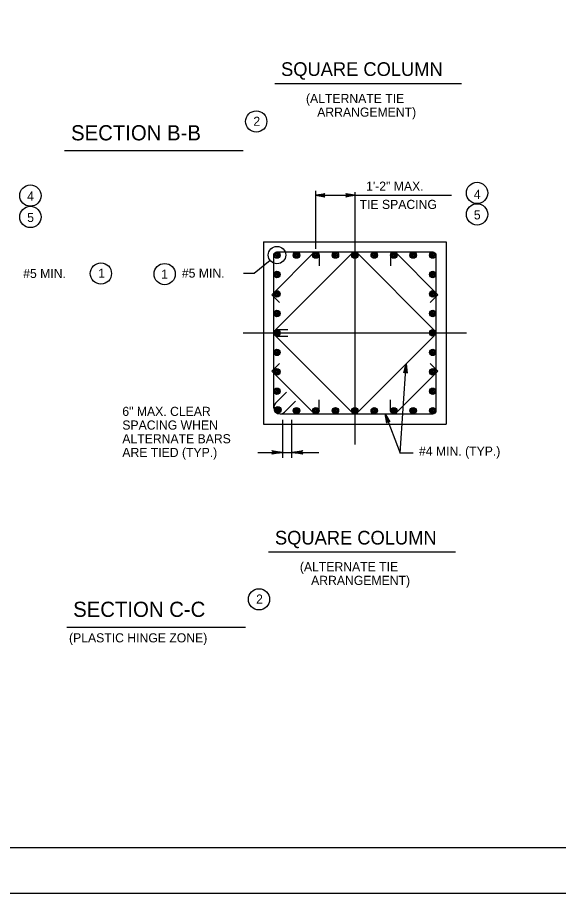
# Model space of a CAD drawing. Extents: x 646165 to 651486, y 296916 to 299292.
# Drawn here: x 648407.1 to 648585, y 296916.2 to 297204.4 of the extents above; entities that cross this region are included whole.
import ezdxf

# ---------------------------------------------------------------- set-up
doc = ezdxf.new("R2010")
doc.units = 0
for name, color, linetype in [('2', 7, 'Continuous'), ('50', 7, 'Continuous'), ('51', 7, 'Continuous'), ('52', 7, 'Continuous'), ('53', 7, 'Continuous'), ('54', 7, 'Continuous'), ('PLT-BNDY', 7, 'Continuous')]:
    doc.layers.add(name, color=color, linetype=linetype)

msp = doc.modelspace()

# ---------------------------------------------------------------- linework, layer by layer
at = {"layer": '2'}
msp.add_line((648933.59, 296931.25), (648147.59, 296931.25), dxfattribs=at)
at = {"layer": '50'}
for p, q in [((648518.06, 297147.01), (648518.06, 297064)), ((648481.39, 297100.67), (648554.73, 297100.67))]:
    msp.add_line(p, q, dxfattribs=at)
at = {"layer": '51'}
for p, q in [((648488.06, 297130.67), (648488.06, 297070.67)), ((648488.06, 297130.67), (648548.06, 297130.67)), ((648548.06, 297130.67), (648548.06, 297070.67)), ((648488.06, 297070.67), (648548.06, 297070.67))]:
    msp.add_line(p, q, dxfattribs=at)
at = {"layer": '52'}
for p, q in [((648505.26, 297128.33), (648505.26, 297147.42)), ((648505.26, 297145.93), (648549.84, 297145.93)), ((648490.23, 297124.47), (648484.91, 297120.16)), ((648484.91, 297120.16), (648481.41, 297120.16)), ((648532.95, 297061.15), (648534.91, 297090.47)), ((648528.03, 297074), (648532.95, 297061.15)), ((648494.37, 297059.52), (648494.37, 297072.12)), ((648497.33, 297059.52), (648497.33, 297072.12)), ((648486.21, 297061.37), (648494.37, 297061.37)), ((648494.37, 297061.37), (648497.33, 297061.37)), ((648497.33, 297061.37), (648506.23, 297061.37)), ((648537.19, 297061.15), (648532.95, 297061.15))]:
    msp.add_line(p, q, dxfattribs=at)
for points in [[(648505.26, 297145.93), (648508.24, 297146.49), (648508.13, 297146.41), (648508.01, 297146.33), (648507.95, 297146.23), (648507.89, 297146.13), (648507.88, 297146.03), (648507.86, 297145.93), (648507.88, 297145.83), (648507.89, 297145.73), (648507.95, 297145.63), (648508.01, 297145.53), (648508.13, 297145.45), (648508.24, 297145.37), (648505.26, 297145.93), (648508.13, 297145.45), (648508.01, 297145.53), (648505.26, 297145.93), (648507.95, 297145.63), (648507.89, 297145.73), (648505.26, 297145.93), (648507.88, 297145.83), (648507.86, 297145.93), (648505.26, 297145.93), (648507.88, 297146.03), (648507.89, 297146.13), (648505.26, 297145.93), (648507.95, 297146.23), (648508.01, 297146.33), (648505.26, 297145.93), (648508.13, 297146.41)], [(648518.06, 297145.93), (648515.08, 297145.37), (648515.19, 297145.45), (648515.31, 297145.53), (648515.37, 297145.63), (648515.42, 297145.73), (648515.44, 297145.83), (648515.46, 297145.93), (648515.44, 297146.03), (648515.42, 297146.13), (648515.37, 297146.23), (648515.31, 297146.33), (648515.19, 297146.41), (648515.08, 297146.49), (648518.06, 297145.93), (648515.19, 297146.41), (648515.31, 297146.33), (648518.06, 297145.93), (648515.37, 297146.23), (648515.42, 297146.13), (648518.06, 297145.93), (648515.44, 297146.03), (648515.46, 297145.93), (648518.06, 297145.93), (648515.44, 297145.83), (648515.42, 297145.73), (648518.06, 297145.93), (648515.37, 297145.63), (648515.31, 297145.53), (648518.06, 297145.93), (648515.19, 297145.45)], [(648534.91, 297090.47), (648535.27, 297087.46), (648535.2, 297087.58), (648535.13, 297087.69), (648535.03, 297087.76), (648534.94, 297087.83), (648534.84, 297087.85), (648534.74, 297087.87), (648534.64, 297087.86), (648534.54, 297087.85), (648534.43, 297087.8), (648534.33, 297087.75), (648534.24, 297087.64), (648534.16, 297087.53), (648534.91, 297090.47), (648534.24, 297087.64), (648534.33, 297087.75), (648534.91, 297090.47), (648534.43, 297087.8), (648534.54, 297087.85), (648534.91, 297090.47), (648534.64, 297087.86), (648534.74, 297087.87), (648534.91, 297090.47), (648534.84, 297087.85), (648534.94, 297087.83), (648534.91, 297090.47), (648535.03, 297087.76), (648535.13, 297087.69), (648534.91, 297090.47), (648535.2, 297087.58)], [(648528.03, 297074), (648529.62, 297071.42), (648529.51, 297071.5), (648529.39, 297071.57), (648529.28, 297071.59), (648529.16, 297071.61), (648529.06, 297071.59), (648528.96, 297071.57), (648528.87, 297071.52), (648528.79, 297071.47), (648528.72, 297071.38), (648528.64, 297071.29), (648528.61, 297071.15), (648528.58, 297071.02), (648528.03, 297074), (648528.61, 297071.15), (648528.64, 297071.29), (648528.03, 297074), (648528.72, 297071.38), (648528.79, 297071.47), (648528.03, 297074), (648528.87, 297071.52), (648528.96, 297071.57), (648528.03, 297074), (648529.06, 297071.59), (648529.16, 297071.61), (648528.03, 297074), (648529.28, 297071.59), (648529.39, 297071.57), (648528.03, 297074), (648529.51, 297071.5)]]:
    msp.add_lwpolyline(points, dxfattribs=at)
for centre, radius in [((648485.63, 297170.22), 3.5), ((648411.37, 297145.85), 3.5), ((648558.25, 297146.71), 3.5), ((648411.37, 297138.81), 3.5), ((648558.25, 297139.66), 3.5), ((648492.46, 297126.27), 2.87), ((648434.55, 297120.21), 3.5), ((648455.52, 297120.01), 3.5), ((648486.55, 297013.02), 3.5)]:
    msp.add_circle(centre, radius, dxfattribs=at)
at = {"layer": '53'}
for p, q in [((648491.71, 297182.7), (648553.12, 297182.7)), ((648422.61, 297160.67), (648481.36, 297160.67)), ((648489.71, 297028.65), (648551.12, 297028.65)), ((648423.31, 297003.91), (648482.06, 297003.91))]:
    msp.add_line(p, q, dxfattribs=at)
at = {"layer": '54'}
for p, q in [((648490.74, 297113.21), (648504.5, 297127.02)), ((648491.39, 297076.07), (648491.4, 297126.27)), ((648492, 297101.63), (648517.3, 297127.02)), ((648492.46, 297127.34), (648543.66, 297127.34)), ((648506.33, 297126.27), (648506.33, 297122.74)), ((648544.34, 297101.4), (648518.81, 297127.02)), ((648529.79, 297126.27), (648529.79, 297122.74)), ((648545.38, 297113.21), (648531.61, 297127.02)), ((648544.73, 297126.27), (648544.73, 297075.07)), ((648493.24, 297110.71), (648490.74, 297113.21)), ((648542.88, 297110.71), (648545.38, 297113.21)), ((648491.75, 297099.96), (648517.3, 297074.32)), ((648492.46, 297101.74), (648495.99, 297101.74)), ((648492.46, 297099.6), (648495.99, 297099.6)), ((648544.12, 297099.71), (648518.81, 297074.32)), ((648493.24, 297090.62), (648490.74, 297088.13)), ((648542.88, 297090.62), (648545.38, 297088.13)), ((648490.74, 297088.13), (648504.5, 297074.32)), ((648545.38, 297088.13), (648531.61, 297074.32)), ((648492, 297077.53), (648495.61, 297081.15)), ((648494.92, 297074.61), (648498.54, 297078.22)), ((648506.33, 297075.07), (648506.33, 297078.6)), ((648529.79, 297075.07), (648529.79, 297078.6)), ((648493.46, 297074), (648543.66, 297074))]:
    msp.add_line(p, q, dxfattribs=at)
for points in [[(648490.96, 297061.8), (648491.09, 297061.55), (648494.37, 297061.37), (648490.96, 297061.8), (648490.79, 297061.95), (648494.37, 297061.37), (648491.09, 297061.21), (648490.97, 297060.97), (648494.37, 297061.37), (648490.79, 297060.8), (648490.97, 297060.97)], [(648500.74, 297060.94), (648500.61, 297061.19), (648497.33, 297061.37), (648500.74, 297060.94), (648500.91, 297060.79), (648497.33, 297061.37), (648500.61, 297061.53), (648500.73, 297061.78), (648497.33, 297061.37), (648500.91, 297061.94), (648500.73, 297061.78)]]:
    msp.add_lwpolyline(points, dxfattribs=at)
for centre, radius in [((648492.46, 297126.27), 1.07), ((648492.46, 297126.27), 0.8), ((648492.46, 297126.27), 0.533), ((648492.46, 297126.27), 0.267), ((648498.86, 297126.27), 1.07), ((648498.86, 297126.27), 0.8), ((648498.86, 297126.27), 0.533), ((648498.86, 297126.27), 0.267), ((648505.26, 297126.27), 1.07), ((648505.26, 297126.27), 0.8), ((648505.26, 297126.27), 0.533), ((648505.26, 297126.27), 0.267), ((648511.66, 297126.27), 1.07), ((648511.66, 297126.27), 0.8), ((648511.66, 297126.27), 0.533), ((648511.66, 297126.27), 0.267), ((648518.06, 297126.27), 1.07), ((648518.06, 297126.27), 0.8), ((648518.06, 297126.27), 0.533), ((648518.06, 297126.27), 0.267), ((648524.46, 297126.27), 1.07), ((648524.46, 297126.27), 0.8), ((648524.46, 297126.27), 0.533), ((648524.46, 297126.27), 0.267), ((648530.86, 297126.27), 1.07), ((648530.86, 297126.27), 0.8), ((648530.86, 297126.27), 0.533), ((648530.86, 297126.27), 0.267), ((648537.26, 297126.27), 1.07), ((648537.26, 297126.27), 0.8), ((648537.26, 297126.27), 0.533), ((648537.26, 297126.27), 0.267), ((648543.66, 297126.27), 1.07), ((648543.66, 297126.27), 0.8), ((648543.66, 297126.27), 0.533), ((648543.66, 297126.27), 0.267), ((648492.46, 297119.87), 1.07), ((648492.46, 297119.87), 0.8), ((648492.46, 297119.87), 0.533), ((648492.46, 297119.87), 0.267), ((648543.66, 297119.87), 1.07), ((648543.66, 297119.87), 0.8), ((648543.66, 297119.87), 0.533), ((648543.66, 297119.87), 0.267), ((648492.46, 297113.47), 1.07), ((648492.46, 297113.47), 0.8), ((648492.46, 297113.47), 0.533), ((648492.46, 297113.47), 0.267), ((648543.66, 297113.47), 1.07), ((648543.66, 297113.47), 0.8), ((648543.66, 297113.47), 0.533), ((648543.66, 297113.47), 0.267), ((648492.46, 297107.07), 1.07), ((648492.46, 297107.07), 0.8), ((648492.46, 297107.07), 0.533), ((648543.66, 297107.07), 1.07), ((648543.66, 297107.07), 0.8), ((648543.66, 297107.07), 0.533), ((648492.46, 297107.07), 0.267), ((648543.66, 297107.07), 0.267), ((648492.46, 297100.67), 1.07), ((648492.46, 297100.67), 0.8), ((648492.46, 297100.67), 0.533), ((648492.46, 297100.67), 0.267), ((648543.66, 297100.67), 1.07), ((648543.66, 297100.67), 0.8), ((648543.66, 297100.67), 0.533), ((648543.66, 297100.67), 0.267), ((648492.46, 297094.27), 1.07), ((648492.46, 297094.27), 0.8), ((648492.46, 297094.27), 0.533), ((648492.46, 297094.27), 0.267), ((648543.66, 297094.27), 1.07), ((648543.66, 297094.27), 0.8), ((648543.66, 297094.27), 0.533), ((648543.66, 297094.27), 0.267), ((648492.46, 297087.87), 1.07), ((648492.46, 297087.87), 0.8), ((648492.46, 297087.87), 0.533), ((648492.46, 297087.87), 0.267), ((648543.66, 297087.87), 1.07), ((648543.66, 297087.87), 0.8), ((648543.66, 297087.87), 0.533), ((648543.66, 297087.87), 0.267), ((648492.46, 297081.47), 1.07), ((648492.46, 297081.47), 0.8), ((648492.46, 297081.47), 0.533), ((648492.46, 297081.47), 0.267), ((648543.66, 297081.47), 1.07), ((648543.66, 297081.47), 0.8), ((648543.66, 297081.47), 0.533), ((648543.66, 297081.47), 0.267), ((648492.75, 297075.36), 1.07), ((648492.75, 297075.36), 0.8), ((648492.75, 297075.36), 0.533), ((648498.86, 297075.07), 1.07), ((648498.86, 297075.07), 0.8), ((648505.26, 297075.07), 1.07), ((648505.26, 297075.07), 0.8), ((648511.66, 297075.07), 1.07), ((648511.66, 297075.07), 0.8), ((648518.06, 297075.07), 1.07), ((648518.06, 297075.07), 0.8), ((648524.46, 297075.07), 1.07), ((648524.46, 297075.07), 0.8), ((648530.86, 297075.07), 1.07), ((648530.86, 297075.07), 0.8), ((648537.26, 297075.07), 1.07), ((648537.26, 297075.07), 0.8), ((648543.66, 297075.07), 1.07), ((648543.66, 297075.07), 0.8), ((648492.75, 297075.36), 0.267), ((648498.86, 297075.07), 0.533), ((648498.86, 297075.07), 0.267), ((648505.26, 297075.07), 0.533), ((648505.26, 297075.07), 0.267), ((648511.66, 297075.07), 0.533), ((648511.66, 297075.07), 0.267), ((648518.06, 297075.07), 0.533), ((648518.06, 297075.07), 0.267), ((648524.46, 297075.07), 0.533), ((648524.46, 297075.07), 0.267), ((648530.86, 297075.07), 0.533), ((648530.86, 297075.07), 0.267), ((648537.26, 297075.07), 0.533), ((648537.26, 297075.07), 0.267), ((648543.66, 297075.07), 0.533), ((648543.66, 297075.07), 0.267)]:
    msp.add_circle(centre, radius, dxfattribs=at)
msp.add_arc((648493.46, 297076.07), 2.07, 135, 315, dxfattribs=at)
at = {"layer": 'PLT-BNDY'}
msp.add_lwpolyline([(648107.59, 297510.25), (648948.59, 297510.25), (648948.59, 296916.25), (648107.59, 296916.25)], close=True, dxfattribs=at)

# ---------------------------------------------------------------- texts
at = {"layer": '53'}
for s, height, p in [('SQUARE COLUMN', 4.5, (648493.79, 297185.2)), ('(ALTERNATE TIE', 3, (648501.99, 297176.3)), ('ARRANGEMENT)', 3, (648505.68, 297171.8)), ('2', 3, (648484.69, 297168.79)), ('SECTION B-B', 5, (648424.73, 297164)), ('1\'-2" MAX.', 3, (648521.76, 297147.44)), ('4', 3, (648410.31, 297144.19)), ('4', 3, (648557.2, 297144.76)), ('TIE SPACING', 3, (648519.63, 297141.44)), ('5', 3, (648410.31, 297137.15)), ('5', 3, (648557.2, 297138)), ('#5 MIN.', 3, (648409, 297118.73)), ('1', 3, (648433.68, 297118.8)), ('1', 3, (648454.37, 297118.47)), ('#5 MIN.', 3, (648461.18, 297118.85)), ('6" MAX. CLEAR', 3, (648441.6, 297073.35)), ('SPACING WHEN', 3, (648441.6, 297068.85)), ('ALTERNATE BARS', 3, (648441.6, 297064.35)), ('ARE TIED (TYP.)', 3, (648441.6, 297059.85)), ('#4 MIN. (TYP.)', 3, (648539.16, 297060.25)), ('SQUARE COLUMN', 4.5, (648491.79, 297031.05)), ('(ALTERNATE TIE', 3, (648499.99, 297022.25)), ('ARRANGEMENT)', 3, (648503.68, 297017.75)), ('2', 3, (648485.6, 297011.6)), ('SECTION C-C', 5, (648425.43, 297007.24)), ('(PLASTIC HINGE ZONE)', 3, (648424.07, 296998.85))]:
    msp.add_text(s, height=height, dxfattribs=at).set_placement(p)

doc.saveas('drawing.dxf')
